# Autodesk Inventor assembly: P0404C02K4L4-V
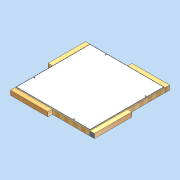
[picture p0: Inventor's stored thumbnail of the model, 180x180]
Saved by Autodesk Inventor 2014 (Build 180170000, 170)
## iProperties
Created: 2011-04
Part Number: P0404C02K4L4-V
Document SubType Name: Assembly
Designer: david.appleford
Mass: 29000 g
Surface Area: 36920.7 cm^2
Volume: 120070 cm^3
Density: 0.241525 g/cm^3
Description: 1w x 1w 02 Ceiling Panel - 4 Locks 4 Lugs
Cost Center: £107.00
Justset: False
Author: david.appleford
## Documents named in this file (3)
- C:\Documents and Settings\john.everitt\Local Settings\My Documents\Vault\Production MkII\VIRTUAL ELEMENTS\Virtual Ceilings\Ceiling MgO & Timber Frame\P0404C02K4L4-V.iam
- C:\Documents and Settings\john.everitt\Local Settings\My Documents\Vault\Production MkII\VIRTUAL ELEMENTS\Virtual Lugs\Superceded Lugs\LA02C3V.ipt
- C:\Documents and Settings\john.everitt\Local Settings\My Documents\Vault\Production MkII\VIRTUAL ELEMENTS\Virtual Ceilings\Ceiling MgO & Timber Frame\P0404C02K4-V.ipt
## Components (5 placed, 2 different names)
1. P0404C02K4-V:1 — Mate:1, Flush:1, Flush:2, Mate:2, Flush:3, Flush:4, Mate:4, Flush:7, Flush:8, Mate:5, Flush:10
2. LA02C3V:1 — Mate:1, Flush:1, Flush:2, Mate:13
3. LA02C3V:2 — Mate:2, Flush:3, Flush:4
4. LA02C3V:3 — Mate:4, Flush:7, Flush:8
5. LA02C3V:4 — Mate:5, Flush:10, Mate:13
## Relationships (12: Flush 7, Mate 5)
- Mate:1: P0404C02K4-V:1 ↔ LA02C3V:1
- Flush:1: P0404C02K4-V:1 ↔ LA02C3V:1
- Flush:2: P0404C02K4-V:1 ↔ LA02C3V:1
- Mate:2: P0404C02K4-V:1 ↔ LA02C3V:2
- Flush:3: P0404C02K4-V:1 ↔ LA02C3V:2
- Flush:4: P0404C02K4-V:1 ↔ LA02C3V:2
- Mate:4: P0404C02K4-V:1 ↔ LA02C3V:3
- Flush:7: P0404C02K4-V:1 ↔ LA02C3V:3
- Flush:8: P0404C02K4-V:1 ↔ LA02C3V:3
- Mate:5: P0404C02K4-V:1 ↔ LA02C3V:4
- Flush:10: P0404C02K4-V:1 ↔ LA02C3V:4
- Mate:13: LA02C3V:1 ↔ LA02C3V:4
## Named parameters: t = 1 mm, Cl = 2 mm
